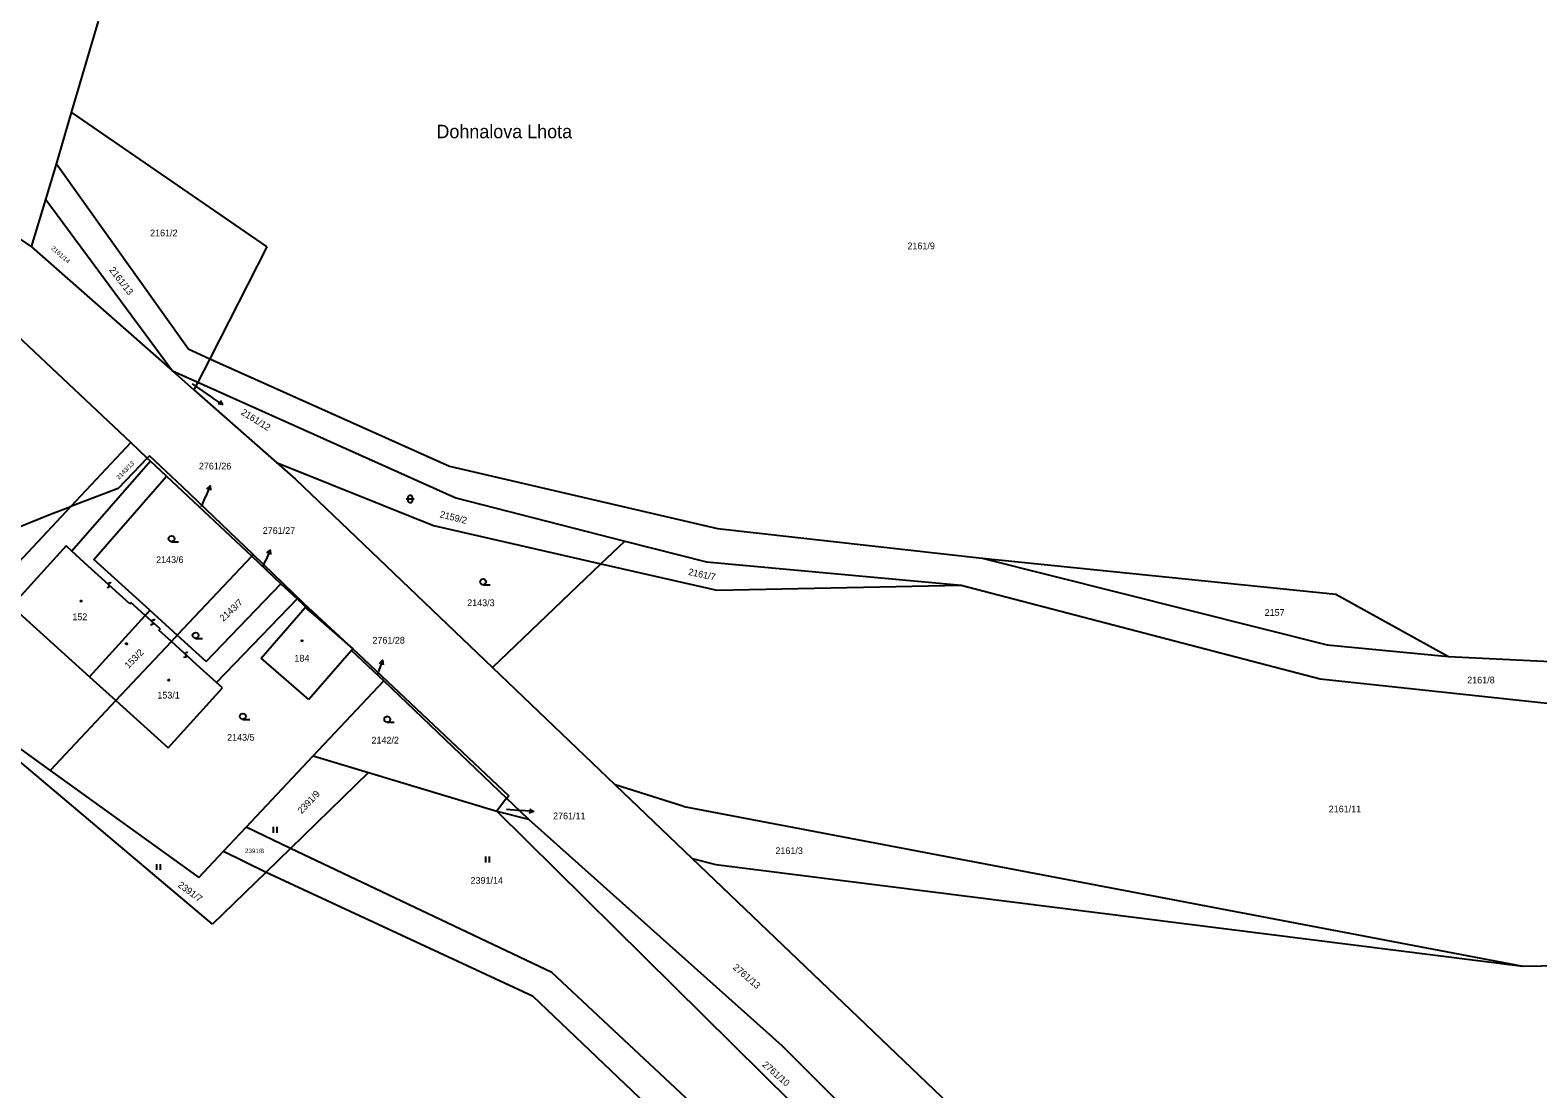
# Model space of a CAD drawing. Extents: x -747792 to -745414, y -1093712 to -1091463.
# Drawn here: x -746621.6 to -746430.6, y -1093249.1 to -1093115.1 of the extents above; entities that cross this region are included whole.
import ezdxf

# ---------------------------------------------------------------- set-up
doc = ezdxf.new("R2010")
doc.units = 0
for name, color, linetype in [('Pracovní_bod JDTM STC_VC', 7, 'Continuous'), ('Pracovní_bod JDTM STC_VC - výška', 7, 'Continuous'), ('Pracovní_bod JDTM STC_VC - číslo', 7, 'Continuous'), ('Pracovní_bod NN - výška', 7, 'Continuous'), ('Pracovní_bod polohopisu', 7, 'Continuous'), ('Pracovní_bod polohopisu - výška', 7, 'Continuous')]:
    doc.layers.add(name, color=color, linetype=linetype)

msp = doc.modelspace()

# ---------------------------------------------------------------- linework, layer by layer
at = {"layer": 'Pracovní_bod JDTM STC_VC - výška'}
for points in [[(-746615.15, -1093187.29), (-746615.1, -1093187.3), (-746615.08, -1093187.34), (-746615.07, -1093187.37), (-746615.08, -1093187.42), (-746615.11, -1093187.45), (-746615.15, -1093187.46), (-746615.2, -1093187.44), (-746615.23, -1093187.41), (-746615.24, -1093187.37), (-746615.23, -1093187.33), (-746615.19, -1093187.29)], [(-746609.38, -1093192.7), (-746609.33, -1093192.71), (-746609.3, -1093192.75), (-746609.29, -1093192.78), (-746609.3, -1093192.83), (-746609.34, -1093192.86), (-746609.38, -1093192.86), (-746609.43, -1093192.85), (-746609.46, -1093192.82), (-746609.47, -1093192.78), (-746609.46, -1093192.73), (-746609.42, -1093192.7)], [(-746587.15, -1093192.3), (-746587.1, -1093192.31), (-746587.08, -1093192.36), (-746587.07, -1093192.39), (-746587.08, -1093192.44), (-746587.11, -1093192.47), (-746587.15, -1093192.47), (-746587.2, -1093192.46), (-746587.23, -1093192.43), (-746587.24, -1093192.39), (-746587.23, -1093192.34), (-746587.19, -1093192.31)], [(-746604.04, -1093197.3), (-746603.99, -1093197.31), (-746603.97, -1093197.36), (-746603.96, -1093197.39), (-746603.97, -1093197.44), (-746604.01, -1093197.47), (-746604.04, -1093197.47), (-746604.08, -1093197.46), (-746604.11, -1093197.43), (-746604.12, -1093197.39), (-746604.11, -1093197.34), (-746604.08, -1093197.31)]]:
    msp.add_lwpolyline(points, close=True, dxfattribs=at)
at = {"layer": 'Pracovní_bod JDTM STC_VC - číslo'}
for points in [[(-746573.94, -1093174.45), (-746573.3, -1093174.45), (-746572.94, -1093174.45)], [(-746603.67, -1093179.86), (-746603.86, -1093179.81), (-746604, -1093179.67), (-746604.05, -1093179.49), (-746604, -1093179.3), (-746603.86, -1093179.16), (-746603.67, -1093179.11), (-746603.48, -1093179.16), (-746603.34, -1093179.3), (-746603.3, -1093179.49), (-746603.34, -1093179.67), (-746603.48, -1093179.81), (-746603.67, -1093179.86), (-746602.8, -1093179.86)], [(-746564.21, -1093185.32), (-746564.4, -1093185.27), (-746564.53, -1093185.13), (-746564.58, -1093184.95), (-746564.53, -1093184.76), (-746564.4, -1093184.62), (-746564.21, -1093184.57), (-746564.02, -1093184.62), (-746563.89, -1093184.76), (-746563.83, -1093184.95), (-746563.89, -1093185.13), (-746564.02, -1093185.27), (-746564.21, -1093185.32), (-746563.33, -1093185.32)], [(-746600.63, -1093192.1), (-746600.82, -1093192.05), (-746600.96, -1093191.91), (-746601.01, -1093191.73), (-746600.96, -1093191.54), (-746600.82, -1093191.4), (-746600.63, -1093191.35), (-746600.44, -1093191.4), (-746600.3, -1093191.54), (-746600.26, -1093191.73), (-746600.3, -1093191.91), (-746600.44, -1093192.05), (-746600.63, -1093192.1), (-746599.76, -1093192.1)], [(-746594.65, -1093202.36), (-746594.84, -1093202.31), (-746594.98, -1093202.17), (-746595.03, -1093201.99), (-746594.98, -1093201.8), (-746594.84, -1093201.66), (-746594.65, -1093201.61), (-746594.46, -1093201.66), (-746594.33, -1093201.8), (-746594.28, -1093201.99), (-746594.33, -1093202.17), (-746594.46, -1093202.31), (-746594.65, -1093202.36), (-746593.78, -1093202.36)], [(-746576.35, -1093202.72), (-746576.54, -1093202.67), (-746576.68, -1093202.53), (-746576.72, -1093202.34), (-746576.68, -1093202.16), (-746576.54, -1093202.02), (-746576.35, -1093201.97), (-746576.16, -1093202.02), (-746576.02, -1093202.16), (-746575.97, -1093202.34), (-746576.02, -1093202.53), (-746576.16, -1093202.67), (-746576.35, -1093202.72), (-746575.47, -1093202.72)], [(-746590.79, -1093215.98), (-746590.79, -1093216.73)], [(-746590.29, -1093216.73), (-746590.29, -1093215.98)], [(-746563.91, -1093219.73), (-746563.91, -1093220.48)], [(-746563.41, -1093220.48), (-746563.41, -1093219.73)], [(-746605.58, -1093220.68), (-746605.58, -1093221.43)], [(-746605.08, -1093221.43), (-746605.08, -1093220.68)]]:
    msp.add_lwpolyline(points, dxfattribs=at)
msp.add_lwpolyline([(-746573.69, -1093174.2), (-746573.64, -1093174.05), (-746573.51, -1093173.96), (-746573.36, -1093173.96), (-746573.23, -1093174.05), (-746573.18, -1093174.2), (-746573.18, -1093174.7), (-746573.23, -1093174.84), (-746573.36, -1093174.94), (-746573.51, -1093174.94), (-746573.64, -1093174.84), (-746573.69, -1093174.7)], close=True, dxfattribs=at)
at = {"layer": 'Pracovní_bod NN - výška'}
for points in [[(-746616.34, -1093125.52), (-746612.92, -1093113.93)], [(-746618.27, -1093132.06), (-746616.34, -1093125.52)], [(-746616.34, -1093125.52), (-746591.61, -1093142.5)], [(-746639.04, -1093130.78), (-746621.42, -1093142.52)], [(-746619.59, -1093136.52), (-746618.27, -1093132.06)], [(-746601.56, -1093155.45), (-746618.27, -1093132.06)], [(-746621.42, -1093142.52), (-746619.59, -1093136.52)], [(-746619.59, -1093136.52), (-746603.57, -1093158.23)], [(-746621.42, -1093142.52), (-746603.57, -1093158.23)], [(-746591.61, -1093142.5), (-746598.85, -1093156.69)], [(-746608.82, -1093167.31), (-746624.59, -1093152.46)], [(-746601.56, -1093155.45), (-746598.85, -1093156.69)], [(-746598.85, -1093156.69), (-746600.37, -1093159.66)], [(-746598.85, -1093156.69), (-746568.46, -1093170.31)], [(-746603.57, -1093158.23), (-746600.37, -1093159.66)], [(-746603.57, -1093158.23), (-746600.86, -1093160.62)], [(-746600.37, -1093159.66), (-746600.86, -1093160.62)], [(-746600.86, -1093160.62), (-746590.38, -1093169.84)], [(-746600.37, -1093159.66), (-746567.68, -1093174.32)], [(-746608.82, -1093167.31), (-746616.43, -1093175.39)], [(-746606.75, -1093169.26), (-746608.82, -1093167.31)], [(-746606.48, -1093168.98), (-746606.75, -1093169.26)], [(-746602.3, -1093172.92), (-746606.48, -1093168.98)], [(-746606.35, -1093169.64), (-746616.32, -1093181.06)], [(-746606.75, -1093169.26), (-746610.46, -1093173.14)], [(-746606.35, -1093169.64), (-746606.75, -1093169.26)], [(-746604.31, -1093171.56), (-746606.35, -1093169.64)], [(-746590.38, -1093169.84), (-746570.5, -1093177.8)], [(-746590.38, -1093169.84), (-746587.97, -1093171.96)], [(-746568.46, -1093170.31), (-746534.49, -1093178.2)], [(-746613.51, -1093182.12), (-746604.31, -1093171.56)], [(-746604.31, -1093171.56), (-746593.53, -1093181.7)], [(-746587.97, -1093171.96), (-746563.01, -1093195.81)], [(-746610.46, -1093173.14), (-746616.43, -1093175.39)], [(-746593.35, -1093181.5), (-746602.3, -1093172.92)], [(-746567.68, -1093174.32), (-746546.26, -1093179.78)], [(-746630.23, -1093180.88), (-746619.04, -1093176.37)], [(-746616.43, -1093175.39), (-746625.58, -1093185.11)], [(-746619.04, -1093176.37), (-746616.43, -1093175.39)], [(-746570.5, -1093177.8), (-746549.27, -1093182.66)], [(-746534.49, -1093178.2), (-746500.97, -1093181.95)], [(-746617.05, -1093180.4), (-746623.94, -1093188.01)], [(-746616.32, -1093181.06), (-746617.05, -1093180.4)], [(-746549.27, -1093182.66), (-746546.26, -1093179.78)], [(-746546.26, -1093179.78), (-746535.91, -1093182.41)], [(-746606.42, -1093188.55), (-746613.51, -1093182.12)], [(-746593.53, -1093181.7), (-746602.95, -1093191.71)], [(-746593.35, -1093181.5), (-746593.53, -1093181.7)], [(-746589.82, -1093185.19), (-746593.53, -1093181.7)], [(-746586.9, -1093187.68), (-746593.35, -1093181.5)], [(-746500.97, -1093181.95), (-746457.24, -1093192.94)], [(-746500.97, -1093181.95), (-746456.18, -1093186.49)], [(-746563.01, -1093195.81), (-746549.27, -1093182.66)], [(-746549.27, -1093182.66), (-746534.59, -1093185.99)], [(-746535.91, -1093182.41), (-746503.64, -1093185.38)], [(-746599.29, -1093195.03), (-746589.82, -1093185.19)], [(-746587.78, -1093187.11), (-746589.82, -1093185.19)], [(-746534.59, -1093185.99), (-746503.64, -1093185.38)], [(-746503.64, -1093185.38), (-746458.14, -1093197.22)], [(-746623.94, -1093188.01), (-746614.06, -1093196.96)], [(-746587.78, -1093187.11), (-746597.99, -1093197.68)], [(-746585.4, -1093189.35), (-746587.78, -1093187.11)], [(-746580.7, -1093193.44), (-746586.9, -1093187.68)], [(-746456.18, -1093186.49), (-746441.9, -1093194.41)], [(-746614.06, -1093196.96), (-746607.01, -1093189.2)], [(-746607.01, -1093189.2), (-746606.42, -1093188.55)], [(-746606.42, -1093188.55), (-746602.95, -1093191.71)], [(-746592.34, -1093194.61), (-746586.74, -1093188.18)], [(-746586.74, -1093188.18), (-746585.4, -1093189.35)], [(-746585.4, -1093189.35), (-746580.7, -1093193.44)], [(-746602.95, -1093191.71), (-746603.7, -1093192.51)], [(-746602.95, -1093191.71), (-746599.29, -1093195.03)], [(-746610.73, -1093199.98), (-746603.7, -1093192.51)], [(-746580.86, -1093193.62), (-746586.3, -1093199.86)], [(-746580.7, -1093193.44), (-746580.86, -1093193.62)], [(-746580.86, -1093193.62), (-746576.78, -1093197.46)], [(-746560.92, -1093212.1), (-746580.7, -1093193.44)], [(-746457.24, -1093192.94), (-746441.9, -1093194.41)], [(-746586.3, -1093199.86), (-746592.34, -1093194.61)], [(-746441.9, -1093194.41), (-746422.94, -1093195.34)], [(-746636.24, -1093196.43), (-746619.07, -1093208.84)], [(-746614.06, -1093196.96), (-746610.73, -1093199.98)], [(-746585.74, -1093206.98), (-746576.78, -1093197.46)], [(-746576.78, -1093197.46), (-746561.23, -1093212.35)], [(-746563.01, -1093195.81), (-746547.46, -1093210.66)], [(-746458.14, -1093197.22), (-746429.37, -1093200.32)], [(-746604.13, -1093205.97), (-746597.23, -1093198.37)], [(-746597.23, -1093198.37), (-746597.99, -1093197.68)], [(-746610.73, -1093199.98), (-746619.07, -1093208.84)], [(-746610.73, -1093199.98), (-746604.13, -1093205.97)], [(-746594.24, -1093216.02), (-746585.74, -1093206.98)], [(-746585.74, -1093206.98), (-746578.72, -1093209.1)], [(-746598.5, -1093228.31), (-746623.42, -1093207.26)], [(-746619.07, -1093208.84), (-746600.22, -1093222.37)], [(-746578.72, -1093209.1), (-746588.6, -1093218.7)], [(-746578.72, -1093209.1), (-746562.47, -1093214)], [(-746538.78, -1093213.4), (-746547.46, -1093210.66)], [(-746547.46, -1093210.66), (-746537.7, -1093220)], [(-746561.23, -1093212.35), (-746562.47, -1093214)], [(-746561.23, -1093212.35), (-746560.92, -1093212.1)], [(-746558.45, -1093214.98), (-746561.23, -1093212.35)], [(-746562.47, -1093214), (-746558.45, -1093214.98)], [(-746562.47, -1093214), (-746510.16, -1093265.66)], [(-746538.78, -1093213.4), (-746432.45, -1093233.6)], [(-746597.12, -1093219.07), (-746594.24, -1093216.02)], [(-746588.6, -1093218.7), (-746594.24, -1093216.02)], [(-746558.45, -1093214.98), (-746526.35, -1093243.65)], [(-746600.22, -1093222.37), (-746597.12, -1093219.07)], [(-746597.12, -1093219.07), (-746591.68, -1093221.7)], [(-746588.6, -1093218.7), (-746591.68, -1093221.7)], [(-746555.51, -1093234.42), (-746588.6, -1093218.7)], [(-746537.7, -1093220), (-746534.72, -1093220.73)], [(-746492.67, -1093263.03), (-746537.7, -1093220)], [(-746591.68, -1093221.7), (-746598.5, -1093228.31)], [(-746591.68, -1093221.7), (-746557.93, -1093237.39)], [(-746534.72, -1093220.73), (-746432.45, -1093233.6)], [(-746432.45, -1093233.6), (-746314.65, -1093231.5)], [(-746534.63, -1093253.91), (-746555.51, -1093234.42)], [(-746557.93, -1093237.39), (-746537.22, -1093257.13)], [(-746499, -1093271.01), (-746526.35, -1093243.65)]]:
    msp.add_lwpolyline(points, dxfattribs=at)
at = {"layer": 'Pracovní_bod polohopisu'}
for points in [[(-746614.23, -1093182.95), (-746616.32, -1093181.06)], [(-746608.97, -1093187.73), (-746614.23, -1093182.95)], [(-746611.87, -1093185.6), (-746611.73, -1093185.66), (-746611.58, -1093185.59), (-746611.54, -1093185.44), (-746611.66, -1093185.22), (-746611.61, -1093185.07), (-746611.46, -1093185.01), (-746611.33, -1093185.08)], [(-746608.97, -1093187.73), (-746608.82, -1093187.56)], [(-746607.01, -1093189.2), (-746608.82, -1093187.56)], [(-746605.13, -1093190.91), (-746607.01, -1093189.2)], [(-746606.34, -1093190.32), (-746606.2, -1093190.38), (-746606.05, -1093190.31), (-746606.01, -1093190.16), (-746606.13, -1093189.93), (-746606.08, -1093189.79), (-746605.93, -1093189.73), (-746605.8, -1093189.79)], [(-746605.13, -1093190.91), (-746605.28, -1093191.08)], [(-746603.7, -1093192.51), (-746605.28, -1093191.08)], [(-746600.05, -1093195.82), (-746603.7, -1093192.51)], [(-746602.15, -1093194.43), (-746602, -1093194.49), (-746601.85, -1093194.42), (-746601.81, -1093194.27), (-746601.93, -1093194.04), (-746601.88, -1093193.9), (-746601.74, -1093193.84), (-746601.6, -1093193.9)], [(-746597.99, -1093197.68), (-746600.05, -1093195.82)]]:
    msp.add_lwpolyline(points, dxfattribs=at)
at = {"layer": 'Pracovní_bod polohopisu - výška'}
for points in [[(-746601.07, -1093159.87), (-746598.48, -1093161.63)], [(-746597.24, -1093162.47), (-746598.48, -1093161.63)], [(-746597.51, -1093161.98), (-746597.24, -1093162.47), (-746597.79, -1093162.4)], [(-746598.79, -1093172.79), (-746599.36, -1093174.18)], [(-746599.21, -1093173.16), (-746598.79, -1093172.79), (-746598.75, -1093173.35)], [(-746599.89, -1093175.46), (-746599.36, -1093174.18)], [(-746592.09, -1093182.94), (-746591.79, -1093182.29)], [(-746591.17, -1093180.92), (-746591.79, -1093182.29)], [(-746591.61, -1093181.28), (-746591.17, -1093180.92), (-746591.15, -1093181.48)], [(-746576.95, -1093194.88), (-746577.44, -1093196.3)], [(-746577.35, -1093195.27), (-746576.95, -1093194.88), (-746576.88, -1093195.44)], [(-746577.56, -1093196.65), (-746577.44, -1093196.3)], [(-746561.23, -1093213.73), (-746559.33, -1093213.9)], [(-746557.84, -1093214.03), (-746559.33, -1093213.9)], [(-746558.31, -1093213.74), (-746557.84, -1093214.03), (-746558.36, -1093214.24)]]:
    msp.add_lwpolyline(points, dxfattribs=at)

# ---------------------------------------------------------------- texts
at = {"layer": 'Pracovní_bod JDTM STC_VC'}
for s, height, p in [('2161/2', 0.85, (-746606.4, -1093141.18)), ('2161/9', 0.85, (-746510.44, -1093142.82)), ('2161/12', 0.05, (-746601.19, -1093159.87)), ('2761/26', 0.05, (-746599.89, -1093175.46)), ('2143/6', 0.85, (-746605.64, -1093182.56)), ('2761/27', 0.05, (-746592.22, -1093182.94)), ('2143/3', 0.85, (-746566.22, -1093188.02)), ('152', 0.85, (-746616.25, -1093189.8)), ('2157', 0.85, (-746465.18, -1093189.25)), ('184', 0.85, (-746588.11, -1093195.04)), ('2761/28', 0.05, (-746577.7, -1093196.65)), ('2161/8', 0.85, (-746439.51, -1093197.8)), ('153/1', 0.85, (-746605.48, -1093199.72)), ('2143/5', 0.85, (-746596.64, -1093205.06)), ('2142/2', 0.85, (-746578.35, -1093205.42)), ('2761/11', 0.05, (-746561.34, -1093213.73)), ('2161/11', 0.85, (-746457.06, -1093214.13)), ('2161/3', 0.85, (-746527.17, -1093219.42)), ('2391/8', 0.57, (-746594.38, -1093219.3)), ('2391/14', 0.85, (-746565.8, -1093223.18))]:
    msp.add_text(s, height=height, dxfattribs=at).set_placement(p)
for s, height, rotation, p in [('2161/14', 0.57, 318.4499, (-746618.98, -1093142.78)), ('2161/13', 0.85, 307.621, (-746611.64, -1093145.45)), ('2143/13', 0.57, 45.321, (-746610.34, -1093172.02)), ('2159/2', 0.85, 345.7227, (-746569.75, -1093176.76)), ('2161/7', 0.85, 348.1292, (-746538.26, -1093184.06)), ('2143/7', 0.85, 42.7427, (-746597.12, -1093190.02)), ('153/2', 0.85, 45.6647, (-746609.12, -1093195.99)), ('2391/9', 0.85, 46.8679, (-746587.19, -1093214.39)), ('2391/7', 0.85, 323.7212, (-746602.97, -1093223.49)), ('2761/13', 0.85, 319.3094, (-746532.63, -1093233.89)), ('2761/10', 0.85, 318.7937, (-746528.91, -1093246.2))]:
    msp.add_text(s, height=height, rotation=rotation, dxfattribs=at).set_placement(p)
at = {"layer": 'Pracovní_bod polohopisu - výška'}
for s, height, p in [('Dohnalova Lhota', 1.7, (-746570.12, -1093128.76)), ('2761/26', 0.85, (-746600.22, -1093170.71)), ('2761/27', 0.85, (-746592.13, -1093178.87)), ('2761/28', 0.85, (-746578.23, -1093192.76)), ('2761/11', 0.85, (-746555.34, -1093215.01))]:
    msp.add_text(s, height=height, dxfattribs=at).set_placement(p)
msp.add_text('2161/12', height=0.85, rotation=328.1329, dxfattribs=at).set_placement((-746594.97, -1093163.69))

doc.saveas('drawing.dxf')
